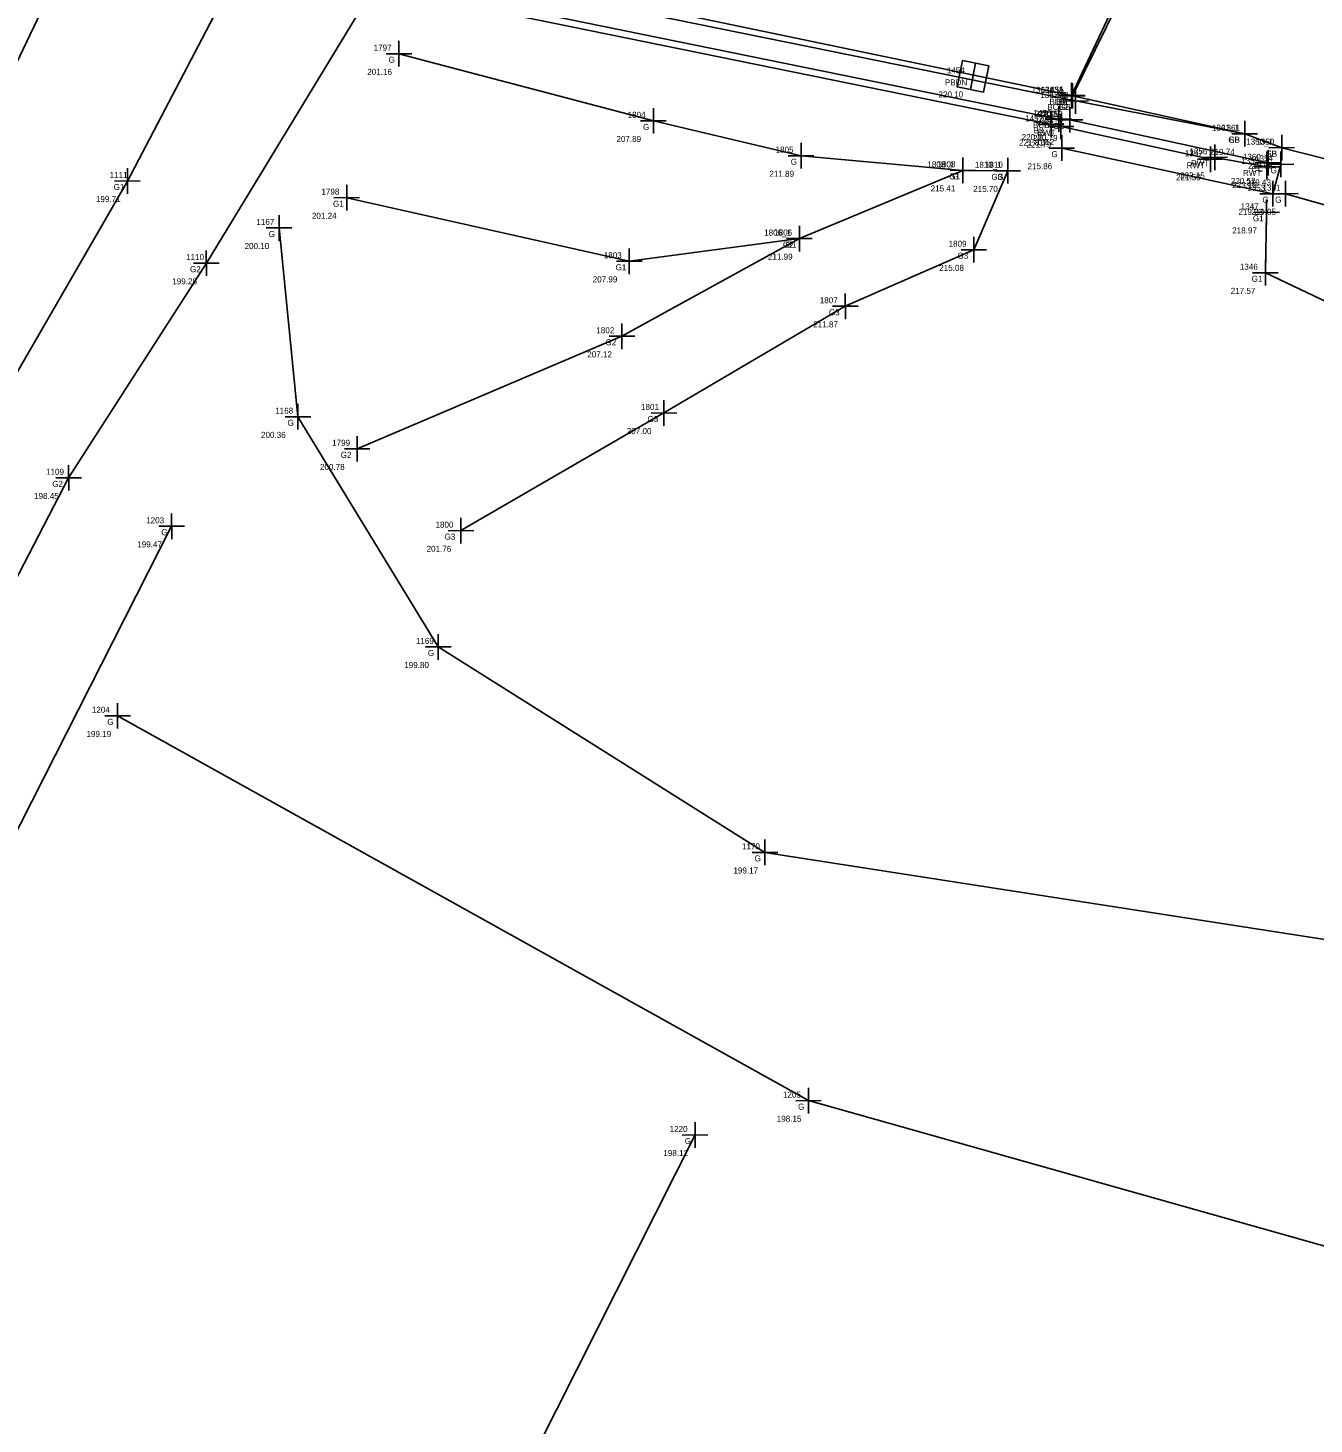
# Model space of a CAD drawing. Extents: x 1155460 to 1157069, y 590691 to 591363.
# Drawn here: x 1156163.3 to 1156227.3, y 591043.1 to 591112.5 of the extents above; entities that cross this region are included whole.
import ezdxf

# ---------------------------------------------------------------- set-up
doc = ezdxf.new("R2010")
doc.units = 0
for name, color, linetype in [('Default', 7, 'Continuous'), ('S_Bridge_Curb', 7, 'Continuous'), ('S_Bridge_Deck', 7, 'Continuous'), ('S_Bridge_Downspout', 7, 'Continuous'), ('S_Bridge_Rail', 7, 'Continuous'), ('S_Curb_Type_2', 7, 'Continuous'), ('S_Field_Code', 7, 'Continuous'), ('S_Ground_Elevation', 7, 'Continuous'), ('S_Ground_LevelString', 7, 'Continuous'), ('S_Guardrail_Beam', 7, 'Continuous'), ('S_Point_Elevation', 7, 'Continuous'), ('S_Point_Name', 7, 'Continuous'), ('S_RetWall_Top', 7, 'Continuous'), ('S_Roadway_Edge_Pavement', 7, 'Continuous'), ('S_Survey_Shot', 7, 'Continuous')]:
    doc.layers.add(name, color=color, linetype=linetype)

msp = doc.modelspace()

# ---------------------------------------------------------------- linework, layer by layer
at = {"layer": 'Default'}
msp.add_line((1156210.302, 591110.114), (1156210.302, 591110.114), dxfattribs=at)
at = {"layer": 'S_Bridge_Curb'}
for points in [[(1156215.406, 591108.888), (1156173.426, 591117.429), (1156114, 591129.694), (1156062.689, 591140.34)], [(1156171.19, 591116.835), (1156214.568, 591107.991)]]:
    msp.add_lwpolyline(points, dxfattribs=at)
at = {"layer": 'S_Bridge_Deck'}
msp.add_lwpolyline([(1156226.576, 591133.311), (1156183.626, 591142.22), (1156124.495, 591154.361), (1156074.386, 591164.613), (1156062.974, 591140.528), (1156113.209, 591130.104), (1156172.043, 591118.153), (1156215.204, 591109.156)], close=True, dxfattribs=at)
at = {"layer": 'S_Bridge_Downspout'}
msp.add_line((1156210.174, 591109.459), (1156210.429, 591110.768), dxfattribs=at)
msp.add_lwpolyline([(1156210.828, 591109.332), (1156209.519, 591109.587), (1156209.775, 591110.896), (1156211.084, 591110.64)], close=True, dxfattribs=at)
at = {"layer": 'S_Bridge_Rail'}
msp.add_lwpolyline([(1156171.038, 591116.523), (1156214.184, 591107.722)], dxfattribs=at)
at = {"layer": 'S_Curb_Type_2'}
msp.add_lwpolyline([(1156215.12, 591107.95), (1156224.977, 591105.812)], dxfattribs=at)
at = {"layer": 'S_Ground_Elevation'}
for points in [[(1156026.409, 590851.848), (1156040.326, 590874.838), (1156058.39, 590911.181), (1156071.104, 590934.748), (1156090.915, 590976.641), (1156113.006, 591016.004), (1156139.021, 591064.633), (1156160.958, 591107.084), (1156169.506, 591124.99), (1156175.806, 591138.805), (1156179.505, 591145.743), (1156187.529, 591159.691), (1156201.686, 591190.317), (1156218.16, 591223.383), (1156239.093, 591270.23), (1156255.242, 591301.39), (1156267.602, 591331.936)], [(1156032.004, 590848.528), (1156045.021, 590871.326), (1156063.975, 590909.148), (1156076.046, 590931.839), (1156096.704, 590975.138), (1156116.985, 591014.069), (1156143.161, 591061.487), (1156168.244, 591104.909), (1156185.364, 591137.606), (1156195.885, 591155.891), (1156211.242, 591187.921), (1156227.119, 591218.986), (1156250.454, 591266.938), (1156267.763, 591287.771), (1156269.11, 591301.043), (1156271.297, 591305.298), (1156273.732, 591308.197), (1156278.168, 591308.152), (1156281.282, 591304.184)], [(1156077.044, 590885.757), (1156078.225, 590900.881), (1156087.55, 590925.658), (1156107.308, 590972.303), (1156125.651, 591009.049), (1156149.087, 591058.822), (1156165.323, 591090.15), (1156172.171, 591100.825), (1156192.51, 591134.279), (1156200.222, 591154.409), (1156220.222, 591188.159), (1156235.359, 591213.271), (1156263.393, 591263.771), (1156283.372, 591293.522)], [(1156181.751, 591111.237), (1156194.405, 591107.899), (1156201.752, 591106.167), (1156209.801, 591105.439), (1156212.032, 591105.417)], [(1156214.72, 591106.546), (1156225.211, 591104.275), (1156225.615, 591105.738)], [(1156179.155, 591104.08), (1156193.207, 591100.92), (1156201.666, 591102.048), (1156209.801, 591105.439)], [(1156184.833, 591087.524), (1156194.928, 591093.375), (1156203.951, 591098.68), (1156210.342, 591101.492), (1156212.032, 591105.417)], [(1156297.688, 591089.841), (1156262.191, 591095.758), (1156236.062, 591101.394), (1156225.846, 591104.279)], [(1156298.682, 591088.195), (1156296.392, 591085.627), (1156279.978, 591085.999), (1156263.481, 591092.536), (1156249.725, 591093.66), (1156229.629, 591098.08), (1156224.845, 591100.347), (1156224.904, 591103.352)], [(1156175.788, 591102.575), (1156176.723, 591093.187), (1156183.705, 591081.742), (1156199.952, 591071.527), (1156234.308, 591066.18), (1156269.105, 591054.717), (1156298.907, 591046.22), (1156315.501, 591043.792)], [(1156179.671, 591091.593), (1156192.838, 591097.19), (1156201.666, 591102.048)], [(1156094.381, 590902.672), (1156095.723, 590923.079), (1156108.724, 590955.142), (1156123.127, 590987.126), (1156133.545, 591010.129), (1156149.574, 591046.793), (1156162.325, 591071.77), (1156170.446, 591087.742)], [(1156167.758, 591078.318), (1156202.118, 591059.183), (1156232.788, 591050.536), (1156272.51, 591040.461), (1156310.212, 591030.52)], [(1156112.102, 590859.336), (1156131.994, 590905.909), (1156151.873, 590952.53), (1156170.469, 590997.174), (1156185.66, 591036.019), (1156196.48, 591057.476)]]:
    msp.add_lwpolyline(points, dxfattribs=at)
at = {"layer": 'S_Ground_LevelString'}
msp.add_line((1156215.252, 591109.143), (1156215.252, 591109.143), dxfattribs=at)
msp.add_lwpolyline([(1156215.252, 591109.143), (1156220.901, 591120.629)], dxfattribs=at)
at = {"layer": 'S_Guardrail_Beam'}
msp.add_lwpolyline([(1156308.743, 591089.76), (1156300.149, 591091.559), (1156290.91, 591093.141), (1156262.028, 591098.261), (1156236.884, 591103.703), (1156225.66, 591106.566), (1156223.814, 591107.26), (1156215.406, 591108.888)], dxfattribs=at)
at = {"layer": 'S_RetWall_Top'}
msp.add_lwpolyline([(1156224.915, 591105.612), (1156222.323, 591106.086), (1156222.107, 591105.992), (1156214.676, 591107.62)], dxfattribs=at)
at = {"layer": 'S_Roadway_Edge_Pavement'}
msp.add_lwpolyline([(1156309.359, 591090.009), (1156300.149, 591091.559), (1156290.91, 591093.141), (1156262.028, 591098.261), (1156236.884, 591103.703), (1156225.66, 591106.566), (1156223.814, 591107.26), (1156215.252, 591109.143)], dxfattribs=at)
at = {"layer": 'S_Survey_Shot'}
for p, q in [((1156181.752, 591110.601), (1156181.75, 591111.874)), ((1156181.115, 591111.236), (1156182.387, 591111.239)), ((1156181.751, 591111.237), (1156181.751, 591111.237)), ((1156215.205, 591108.52), (1156215.203, 591109.793)), ((1156215.253, 591108.506), (1156215.251, 591109.779)), ((1156215.253, 591108.506), (1156215.251, 591109.779)), ((1156215.407, 591108.252), (1156215.404, 591109.524)), ((1156215.407, 591108.252), (1156215.404, 591109.524)), ((1156214.568, 591109.155), (1156215.84, 591109.158)), ((1156214.616, 591109.141), (1156215.888, 591109.144)), ((1156214.616, 591109.141), (1156215.888, 591109.144)), ((1156214.769, 591108.886), (1156216.042, 591108.889)), ((1156214.769, 591108.886), (1156216.042, 591108.889)), ((1156215.204, 591109.156), (1156215.204, 591109.156)), ((1156215.252, 591109.143), (1156215.252, 591109.143)), ((1156215.252, 591109.143), (1156215.252, 591109.143)), ((1156215.406, 591108.888), (1156215.406, 591108.888)), ((1156215.406, 591108.888), (1156215.406, 591108.888)), ((1156194.406, 591107.263), (1156194.403, 591108.536)), ((1156214.186, 591107.086), (1156214.183, 591108.358)), ((1156214.569, 591107.355), (1156214.567, 591108.627)), ((1156214.677, 591106.983), (1156214.675, 591108.256)), ((1156215.121, 591107.314), (1156215.118, 591108.586)), ((1156193.769, 591107.898), (1156195.041, 591107.901)), ((1156194.405, 591107.899), (1156194.405, 591107.899)), ((1156213.548, 591107.721), (1156214.82, 591107.723)), ((1156213.932, 591107.99), (1156215.204, 591107.992)), ((1156214.04, 591107.618), (1156215.312, 591107.621)), ((1156214.184, 591107.722), (1156214.184, 591107.722)), ((1156214.483, 591107.949), (1156215.756, 591107.951)), ((1156214.568, 591107.991), (1156214.568, 591107.991)), ((1156214.676, 591107.62), (1156214.676, 591107.62)), ((1156215.12, 591107.95), (1156215.12, 591107.95)), ((1156223.816, 591106.624), (1156223.813, 591107.897)), ((1156223.816, 591106.624), (1156223.813, 591107.897)), ((1156201.753, 591105.531), (1156201.75, 591106.804)), ((1156214.721, 591105.91), (1156214.719, 591107.182)), ((1156222.324, 591105.45), (1156222.322, 591106.722)), ((1156223.178, 591107.259), (1156224.451, 591107.262)), ((1156223.178, 591107.259), (1156224.451, 591107.262)), ((1156223.814, 591107.26), (1156223.814, 591107.26)), ((1156223.814, 591107.26), (1156223.814, 591107.26)), ((1156225.661, 591105.93), (1156225.658, 591107.203)), ((1156225.661, 591105.93), (1156225.658, 591107.203)), ((1156201.115, 591106.166), (1156202.388, 591106.169)), ((1156201.752, 591106.167), (1156201.752, 591106.167)), ((1156209.803, 591104.803), (1156209.8, 591106.076)), ((1156209.803, 591104.803), (1156209.8, 591106.076)), ((1156212.034, 591104.781), (1156212.031, 591106.054)), ((1156212.034, 591104.781), (1156212.031, 591106.054)), ((1156214.084, 591106.545), (1156215.356, 591106.547)), ((1156214.72, 591106.546), (1156214.72, 591106.546)), ((1156221.471, 591105.99), (1156222.744, 591105.993)), ((1156221.687, 591106.085), (1156222.959, 591106.087)), ((1156222.109, 591105.355), (1156222.106, 591106.628)), ((1156222.107, 591105.992), (1156222.107, 591105.992)), ((1156222.323, 591106.086), (1156222.323, 591106.086)), ((1156224.917, 591104.976), (1156224.914, 591106.248)), ((1156224.978, 591105.176), (1156224.975, 591106.449)), ((1156225.023, 591106.565), (1156226.296, 591106.568)), ((1156225.023, 591106.565), (1156226.296, 591106.568)), ((1156225.616, 591105.101), (1156225.613, 591106.374)), ((1156225.66, 591106.566), (1156225.66, 591106.566)), ((1156225.66, 591106.566), (1156225.66, 591106.566)), ((1156168.245, 591104.273), (1156168.242, 591105.546)), ((1156209.165, 591105.438), (1156210.437, 591105.441)), ((1156209.165, 591105.438), (1156210.437, 591105.441)), ((1156209.801, 591105.439), (1156209.801, 591105.439)), ((1156209.801, 591105.439), (1156209.801, 591105.439)), ((1156211.396, 591105.416), (1156212.669, 591105.419)), ((1156211.396, 591105.416), (1156212.669, 591105.419)), ((1156212.032, 591105.417), (1156212.032, 591105.417)), ((1156212.032, 591105.417), (1156212.032, 591105.417)), ((1156224.279, 591105.611), (1156225.551, 591105.613)), ((1156224.34, 591105.811), (1156225.613, 591105.814)), ((1156224.915, 591105.612), (1156224.915, 591105.612)), ((1156224.977, 591105.812), (1156224.977, 591105.812)), ((1156224.978, 591105.736), (1156226.251, 591105.739)), ((1156225.615, 591105.738), (1156225.615, 591105.738)), ((1156167.608, 591104.908), (1156168.88, 591104.911)), ((1156168.244, 591104.909), (1156168.244, 591104.909)), ((1156179.156, 591103.444), (1156179.154, 591104.716)), ((1156225.212, 591103.639), (1156225.21, 591104.912)), ((1156225.847, 591103.643), (1156225.844, 591104.915)), ((1156178.519, 591104.079), (1156179.791, 591104.081)), ((1156179.155, 591104.08), (1156179.155, 591104.08)), ((1156224.575, 591104.274), (1156225.847, 591104.277)), ((1156224.906, 591102.716), (1156224.903, 591103.988)), ((1156225.21, 591104.277), (1156226.482, 591104.28)), ((1156225.211, 591104.275), (1156225.211, 591104.275)), ((1156225.846, 591104.279), (1156225.846, 591104.279)), ((1156224.268, 591103.351), (1156225.541, 591103.353)), ((1156224.904, 591103.352), (1156224.904, 591103.352)), ((1156175.152, 591102.573), (1156176.424, 591102.576)), ((1156175.789, 591101.938), (1156175.786, 591103.211)), ((1156175.788, 591102.575), (1156175.788, 591102.575)), ((1156201.667, 591101.412), (1156201.665, 591102.685)), ((1156201.667, 591101.412), (1156201.665, 591102.685)), ((1156201.03, 591102.047), (1156202.302, 591102.05)), ((1156201.03, 591102.047), (1156202.302, 591102.05)), ((1156201.666, 591102.048), (1156201.666, 591102.048)), ((1156201.666, 591102.048), (1156201.666, 591102.048)), ((1156210.344, 591100.855), (1156210.341, 591102.128)), ((1156172.172, 591100.189), (1156172.169, 591101.461)), ((1156193.208, 591100.283), (1156193.206, 591101.556)), ((1156209.706, 591101.49), (1156210.979, 591101.493)), ((1156210.342, 591101.492), (1156210.342, 591101.492)), ((1156171.534, 591100.824), (1156172.807, 591100.827)), ((1156172.171, 591100.825), (1156172.171, 591100.825)), ((1156192.571, 591100.918), (1156193.843, 591100.921)), ((1156193.207, 591100.92), (1156193.207, 591100.92)), ((1156224.846, 591099.711), (1156224.844, 591100.983)), ((1156224.209, 591100.345), (1156225.481, 591100.348)), ((1156224.845, 591100.347), (1156224.845, 591100.347)), ((1156203.952, 591098.044), (1156203.95, 591099.316)), ((1156203.315, 591098.679), (1156204.587, 591098.681)), ((1156203.951, 591098.68), (1156203.951, 591098.68)), ((1156192.839, 591096.554), (1156192.836, 591097.826)), ((1156192.201, 591097.188), (1156193.474, 591097.191)), ((1156192.838, 591097.19), (1156192.838, 591097.19)), ((1156176.725, 591092.551), (1156176.722, 591093.823)), ((1156194.929, 591092.739), (1156194.927, 591094.011)), ((1156176.087, 591093.186), (1156177.36, 591093.189)), ((1156176.723, 591093.187), (1156176.723, 591093.187)), ((1156194.292, 591093.374), (1156195.564, 591093.376)), ((1156194.928, 591093.375), (1156194.928, 591093.375)), ((1156179.673, 591090.957), (1156179.67, 591092.229)), ((1156179.035, 591091.591), (1156180.308, 591091.594)), ((1156179.671, 591091.593), (1156179.671, 591091.593)), ((1156165.325, 591089.513), (1156165.322, 591090.786)), ((1156164.687, 591090.148), (1156165.96, 591090.151)), ((1156165.323, 591090.15), (1156165.323, 591090.15)), ((1156170.447, 591087.106), (1156170.445, 591088.378)), ((1156184.834, 591086.888), (1156184.831, 591088.16)), ((1156169.81, 591087.741), (1156171.082, 591087.743)), ((1156170.446, 591087.742), (1156170.446, 591087.742)), ((1156184.196, 591087.522), (1156185.469, 591087.525)), ((1156184.833, 591087.524), (1156184.833, 591087.524)), ((1156183.069, 591081.741), (1156184.342, 591081.743)), ((1156183.707, 591081.106), (1156183.704, 591082.378)), ((1156183.705, 591081.742), (1156183.705, 591081.742)), ((1156167.759, 591077.682), (1156167.757, 591078.954)), ((1156167.122, 591078.316), (1156168.394, 591078.319)), ((1156167.758, 591078.318), (1156167.758, 591078.318)), ((1156199.953, 591070.891), (1156199.951, 591072.164)), ((1156199.316, 591071.526), (1156200.588, 591071.529)), ((1156199.952, 591071.527), (1156199.952, 591071.527)), ((1156202.12, 591058.547), (1156202.117, 591059.819)), ((1156201.482, 591059.182), (1156202.754, 591059.185)), ((1156202.118, 591059.183), (1156202.118, 591059.183)), ((1156196.482, 591056.84), (1156196.479, 591058.112)), ((1156195.844, 591057.475), (1156197.117, 591057.478)), ((1156196.48, 591057.476), (1156196.48, 591057.476))]:
    msp.add_line(p, q, dxfattribs=at)

# ---------------------------------------------------------------- texts
at = {"layer": 'S_Field_Code'}
for s, p in [('G', (1156181.236, 591110.787)), ('PBDN', (1156208.901, 591109.664)), ('BDK', (1156214.103, 591108.706)), ('EP', (1156214.466, 591108.693)), ('L1', (1156214.61, 591108.693)), ('BCB2', (1156213.991, 591108.438)), ('GB', (1156214.591, 591108.438)), ('G', (1156193.89, 591107.449)), ('BCB1', (1156213.283, 591107.541)), ('BIL', (1156213.313, 591107.272)), ('RWT', (1156213.49, 591107.17)), ('CC', (1156214.29, 591107.5)), ('GB', (1156222.999, 591106.81)), ('EP', (1156223.028, 591106.81)), ('G', (1156201.237, 591105.717)), ('G', (1156214.205, 591106.096)), ('GB', (1156224.845, 591106.116)), ('EP', (1156224.873, 591106.116)), ('RWT', (1156220.922, 591105.542)), ('RWT', (1156221.137, 591105.636)), ('RWT', (1156223.729, 591105.162)), ('CC', (1156224.147, 591105.362)), ('G', (1156225.1, 591105.288)), ('G1', (1156167.559, 591104.459)), ('G1', (1156209.116, 591104.989)), ('G', (1156209.286, 591104.989)), ('G3', (1156211.217, 591104.967)), ('G', (1156211.517, 591104.967)), ('G1', (1156178.47, 591103.63)), ('G', (1156224.696, 591103.825)), ('G', (1156225.331, 591103.829)), ('G1', (1156224.22, 591102.902)), ('G', (1156175.273, 591102.125)), ('G2', (1156200.851, 591101.598)), ('G1', (1156200.981, 591101.598)), ('G3', (1156209.528, 591101.041)), ('G2', (1156171.356, 591100.375)), ('G1', (1156192.522, 591100.47)), ('G1', (1156224.16, 591099.897)), ('G3', (1156203.136, 591098.23)), ('G2', (1156192.023, 591096.74)), ('G', (1156176.208, 591092.737)), ('G3', (1156194.113, 591092.925)), ('G2', (1156178.856, 591091.143)), ('G2', (1156164.508, 591089.7)), ('G', (1156169.931, 591087.292)), ('G3', (1156184.018, 591087.074)), ('G', (1156183.19, 591081.292)), ('G', (1156167.243, 591077.868)), ('G', (1156199.437, 591071.077)), ('G', (1156201.603, 591058.733)), ('G', (1156195.966, 591057.026))]:
    msp.add_text(s, height=0.3, dxfattribs=at).set_placement(p)
at = {"layer": 'S_Point_Elevation'}
for s, p in [('201.16', (1156180.176, 591110.188)), ('220.10', (1156208.585, 591109.064)), ('220.09', (1156213.371, 591108.106)), ('220.10', (1156213.535, 591108.093)), ('220.10', (1156213.535, 591108.093)), ('220.78', (1156213.554, 591107.838)), ('220.78', (1156213.554, 591107.838)), ('207.89', (1156192.567, 591106.849)), ('221.81', (1156212.592, 591106.672)), ('220.80', (1156212.721, 591106.941)), ('221.79', (1156212.966, 591106.57)), ('220.79', (1156213.282, 591106.9)), ('219.74', (1156222.09, 591106.21)), ('219.74', (1156222.09, 591106.21)), ('211.89', (1156200.174, 591105.117)), ('215.86', (1156213.012, 591105.496)), ('223.15', (1156220.601, 591105.036)), ('219.66', (1156223.981, 591105.516)), ('219.66', (1156223.981, 591105.516)), ('215.41', (1156208.195, 591104.389)), ('215.41', (1156208.195, 591104.389)), ('215.70', (1156210.311, 591104.367)), ('215.70', (1156210.311, 591104.367)), ('221.59', (1156220.4, 591104.942)), ('220.52', (1156223.127, 591104.762)), ('223.12', (1156223.193, 591104.562)), ('219.43', (1156223.893, 591104.688)), ('199.71', (1156166.678, 591103.859)), ('201.24', (1156177.421, 591103.03)), ('219.23', (1156223.503, 591103.225)), ('219.05', (1156224.141, 591103.229)), ('218.97', (1156223.195, 591102.302)), ('200.10', (1156174.073, 591101.525)), ('211.99', (1156200.103, 591100.998)), ('211.99', (1156200.103, 591100.998)), ('215.08', (1156208.623, 591100.441)), ('199.28', (1156170.477, 591099.775)), ('207.99', (1156191.384, 591099.87)), ('217.57', (1156223.118, 591099.297)), ('211.87', (1156202.357, 591097.63)), ('207.12', (1156191.116, 591096.14)), ('200.36', (1156174.89, 591092.137)), ('207.00', (1156193.081, 591092.325)), ('200.78', (1156177.822, 591090.543)), ('198.45', (1156163.602, 591089.1)), ('199.47', (1156168.736, 591086.692)), ('201.76', (1156183.125, 591086.474)), ('199.80', (1156182.014, 591080.692)), ('199.19', (1156166.209, 591077.268)), ('199.17', (1156198.386, 591070.477)), ('198.15', (1156200.541, 591058.133)), ('198.12', (1156194.903, 591056.426))]:
    msp.add_text(s, height=0.3, dxfattribs=at).set_placement(p)
at = {"layer": 'S_Point_Name'}
for s, p in [('1797', (1156180.49, 591111.387)), ('1454', (1156209.002, 591110.264)), ('1363A_1', (1156213.211, 591109.293)), ('1363A', (1156213.665, 591109.293)), ('1455', (1156213.919, 591109.306)), ('1362_1', (1156213.651, 591109.038)), ('1362', (1156214.149, 591109.038)), ('1804', (1156193.122, 591108.049)), ('1457', (1156212.897, 591107.872)), ('1456', (1156213.297, 591108.141)), ('1358', (1156213.405, 591107.77)), ('1359', (1156213.863, 591108.1)), ('1361_1', (1156222.189, 591107.41)), ('1361', (1156222.688, 591107.41)), ('1352', (1156213.449, 591106.696)), ('1350_1', (1156223.893, 591106.716)), ('1350', (1156224.391, 591106.716)), ('1805', (1156200.483, 591106.318)), ('1357', (1156220.834, 591106.142)), ('1356', (1156221.066, 591106.236)), ('1355', (1156223.644, 591105.762)), ('1360', (1156223.722, 591105.962)), ('1354', (1156224.33, 591105.888)), ('1111', (1156167.363, 591105.059)), ('1808_1', (1156208.034, 591105.59)), ('1808', (1156208.533, 591105.59)), ('1810_1', (1156210.395, 591105.567)), ('1810', (1156210.894, 591105.567)), ('1353', (1156223.94, 591104.425)), ('1351', (1156224.705, 591104.429)), ('1798', (1156177.896, 591104.23)), ('1347', (1156223.617, 591103.502)), ('1167', (1156174.659, 591102.725)), ('1806_1', (1156199.913, 591102.198)), ('1806', (1156200.412, 591102.198)), ('1809', (1156209.088, 591101.641)), ('1110', (1156171.162, 591100.975)), ('1803', (1156191.938, 591101.07)), ('1346', (1156223.574, 591100.497)), ('1807', (1156202.68, 591098.83)), ('1802', (1156191.569, 591097.34)), ('1168', (1156175.597, 591093.337)), ('1801', (1156193.79, 591093.525)), ('1799', (1156178.427, 591091.743)), ('1109', (1156164.199, 591090.3)), ('1203', (1156169.177, 591087.892)), ('1800', (1156183.567, 591087.674)), ('1169', (1156182.593, 591081.892)), ('1204', (1156166.476, 591078.468)), ('1170', (1156198.811, 591071.677)), ('1205', (1156200.85, 591059.333)), ('1220', (1156195.212, 591057.626))]:
    msp.add_text(s, height=0.3, dxfattribs=at).set_placement(p)

doc.saveas('drawing.dxf')
